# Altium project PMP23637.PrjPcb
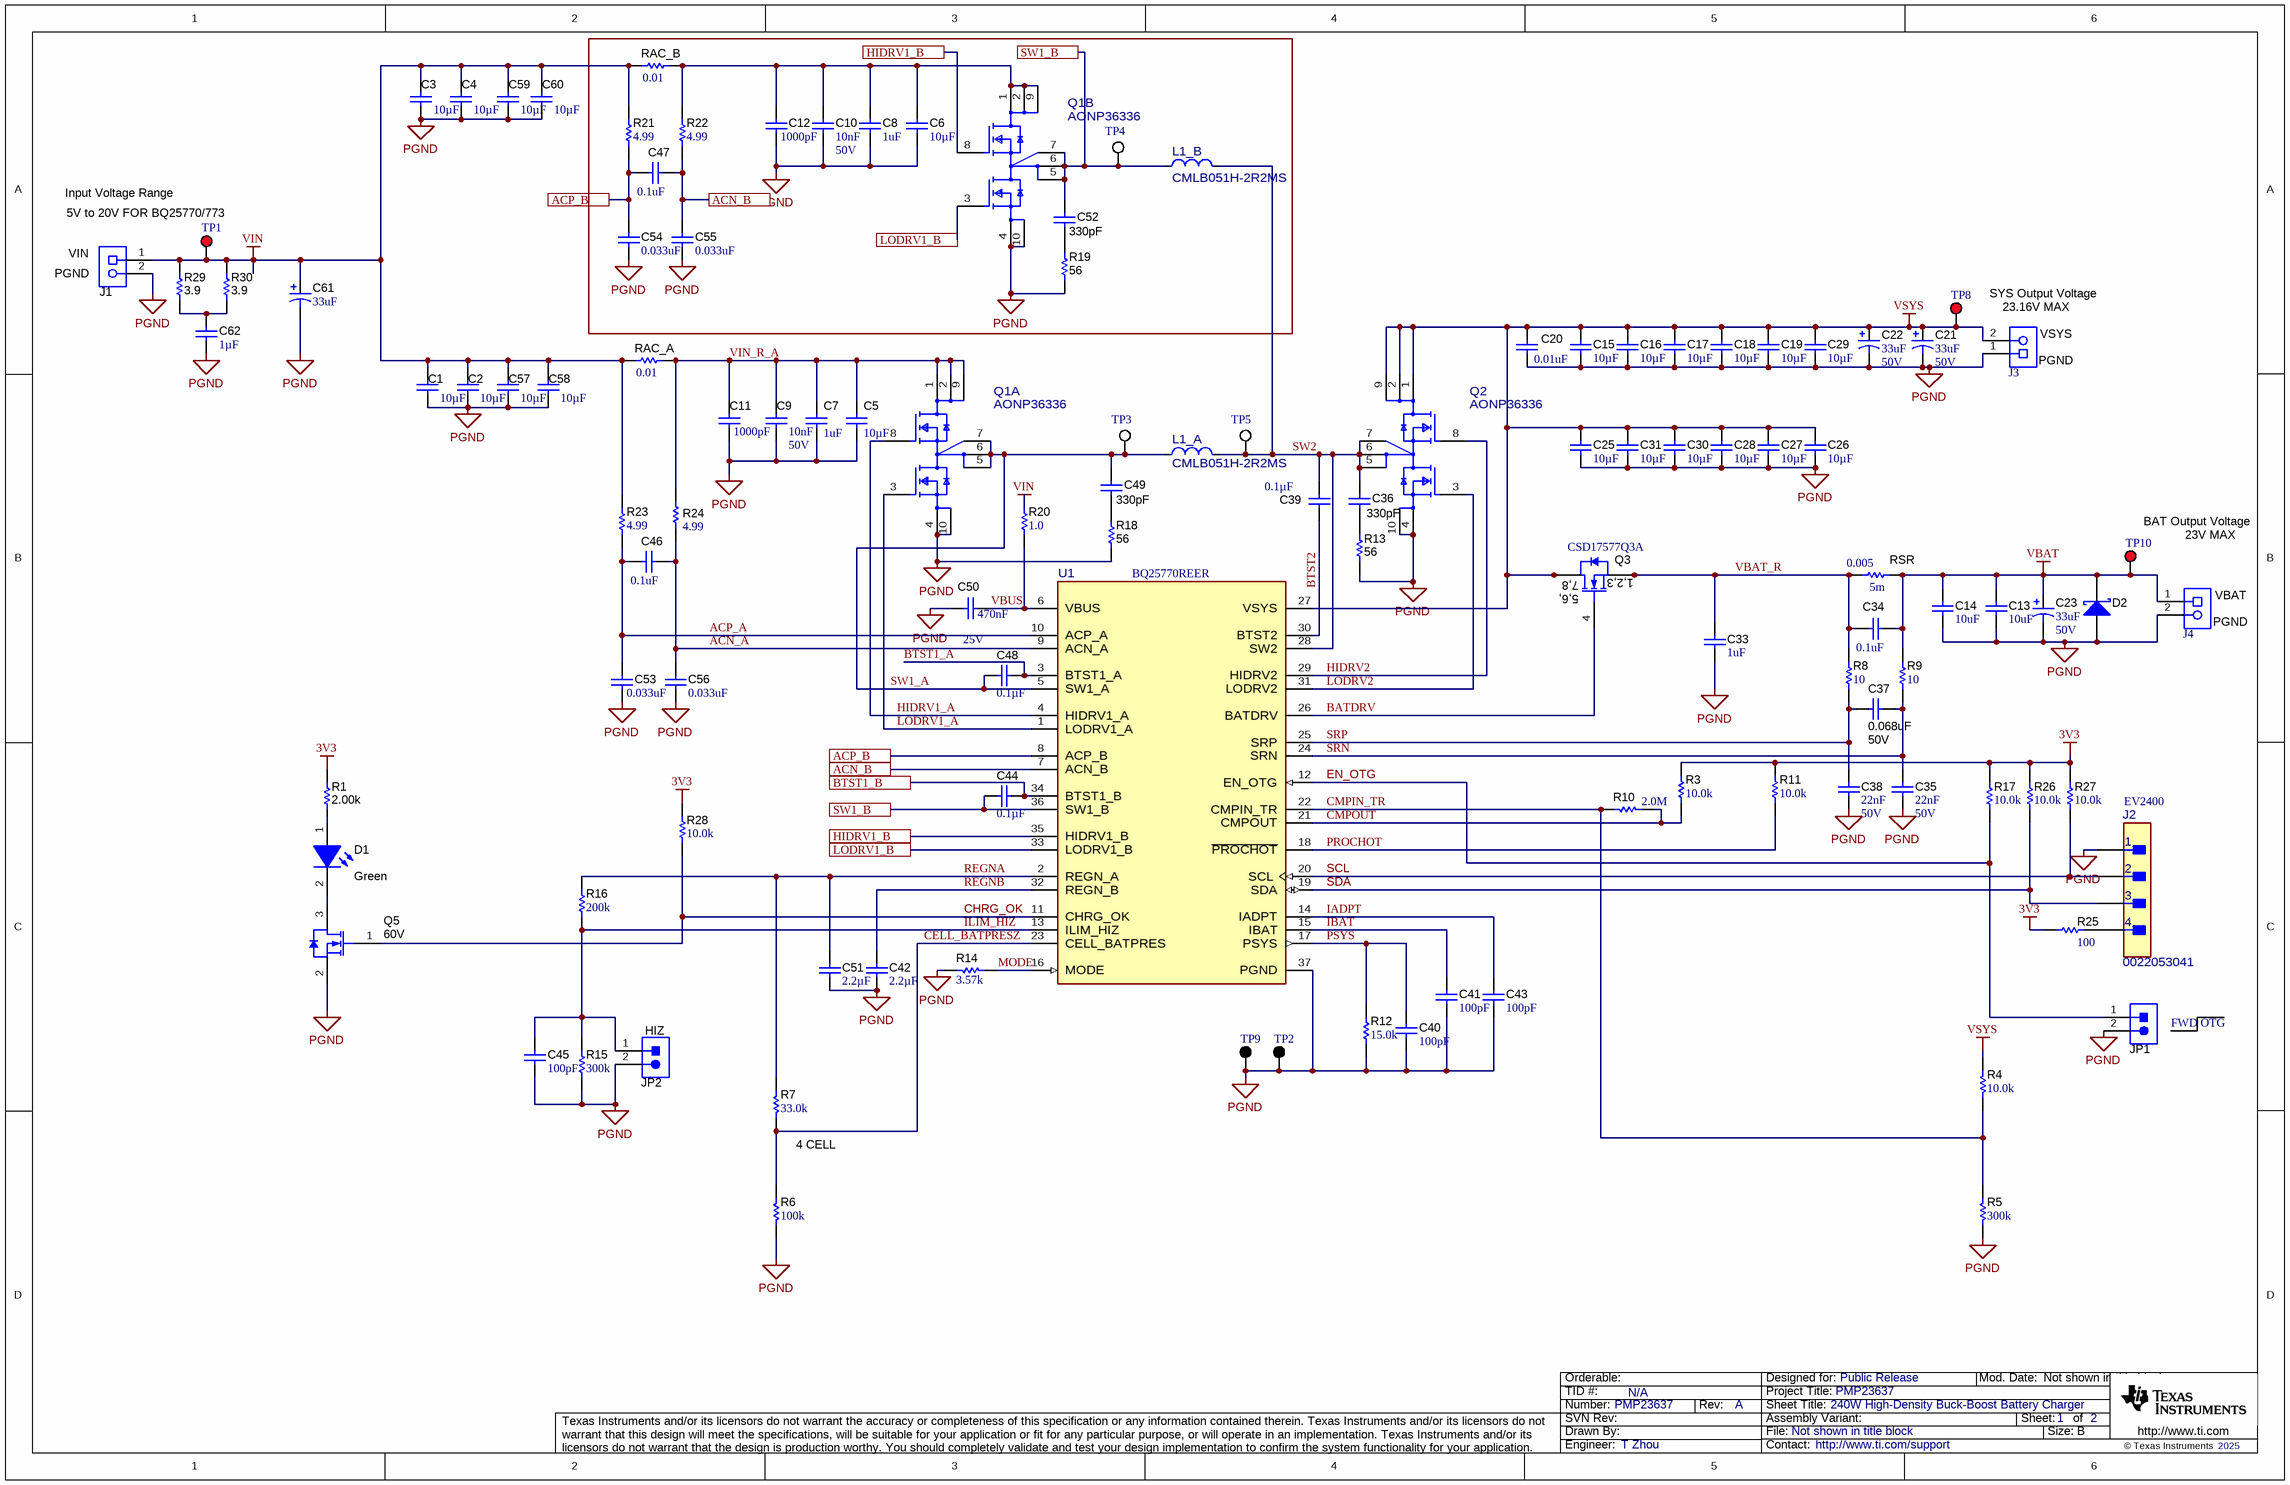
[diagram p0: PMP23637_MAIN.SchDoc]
CopyrightYear: 2025; PCB_Layout: T Zhou; PCB_Rev: A; PRJ_Customer: Public Release; PRJ_Engineer: T Zhou; PRJ_Number: PMP23637; PRJ_Title: PMP23637; SCH_Rev: A; TechSupport: http://www.ti.com/support; TID: N/A
2 sheets, 145 parts. Net scope: global (net labels, ports and power ports of the same name join across sheets).
Board file: PMP23637-PCB.PcbDoc
Sheets:
  PMP23637_MAIN.SchDoc
  PMP23637_Hardware.SchDoc

## Sheet PMP23637_MAIN.SchDoc: 240W High-Density Buck-Boost Battery Charger
size 431 x 279 mm; Date: Not shown in title block; ApprovedBy: Not shown in title block; CheckedBy: Not shown in title block; Author: Not shown in title block; CompanyName: Not shown in title block; Engineer: Not shown in title block; Organization: Not shown in title block; Address1: Not shown in title block; Address2: Not shown in title block; Address3: Not shown in title block; Address4: Not shown in title block; DocumentNumber: 1; Revision: Use project parameter SCH_Rev; SheetNumber: 1; SheetTotal: 2; PageSetup: Record=PageOptions¦CenterHorizontal=True¦CenterVertical=True¦PrintScale=1.00¦XCorrection=1.00¦YCorrection=1.00¦PrintKind=0¦BorderSize=5000000¦LeftOffset=0¦BottomOffset=0¦Orientation=2¦PaperLength=1000¦PaperWidth=1000¦Scale=100¦PaperSource=15¦PrintQuality=600¦MediaType=1¦DitherType=10¦PaperKind=Letter¦PrintScaleMode=1

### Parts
C1  ValueDisplayed: 10µF  [0805_HV1]  (hidden comment: C2012JB1V106K125AC)
C2  ValueDisplayed: 10µF  [0805_HV1]  (hidden comment: C2012JB1V106K125AC)
C3  ValueDisplayed: 10µF  [0805_HV1]  (hidden comment: C2012JB1V106K125AC)
C4  ValueDisplayed: 10µF  [0805_HV1]  (hidden comment: C2012JB1V106K125AC)
C5  ValueDisplayed: 10µF  [0805_HV1]  (hidden comment: C2012JB1V106K125AC)
C6  ValueDisplayed: 10µF  [0805_HV1]  (hidden comment: C2012JB1V106K125AC)
C7  ValueDisplayed: 1uF  [0603S]  (hidden comment: C1608X5R1H105K080AB)
C8  ValueDisplayed: 1uF  [0603S]  (hidden comment: C1608X5R1H105K080AB)
C9  Cap_F: 10nF  VDC_V: 50V  [0603S]  (hidden comment: C0603C103J5RACTU)
C10  Cap_F: 10nF  VDC_V: 50V  [0603S]  (hidden comment: C0603C103J5RACTU)
C11  ValueDisplayed: 1000pF  [0402S]  (hidden comment: 04025C102JAT2A)
C12  ValueDisplayed: 1000pF  [0402S]  (hidden comment: 04025C102JAT2A)
C13  ValueDisplayed: 10uF  [1206_190L]  (hidden comment: GMK316AB7106KL-TR)
C14  ValueDisplayed: 10uF  [1206_190L]  (hidden comment: GMK316AB7106KL-TR)
C15  ValueDisplayed: 10µF  [0805_HV1]  (hidden comment: C2012JB1V106K125AC)
C16  ValueDisplayed: 10µF  [0805_HV1]  (hidden comment: C2012JB1V106K125AC)
C17  ValueDisplayed: 10µF  [0805_HV1]  (hidden comment: C2012JB1V106K125AC)
C18  ValueDisplayed: 10µF  [0805_HV1]  (hidden comment: C2012JB1V106K125AC)
C19  ValueDisplayed: 10µF  [0805_HV1]  (hidden comment: C2012JB1V106K125AC)
C20  ValueDisplayed: 0.01uF  [0603S]  (hidden comment: C0603C103J5RACTU)
C21  ValueDisplayed: 33uF  VDC_V: 50V  [7343-43]  (hidden comment: T521X336M050ATE050)
C22  ValueDisplayed: 33uF  VDC_V: 50V  [7343-43]  (hidden comment: T521X336M050ATE050)
C23  ValueDisplayed: 33uF  VDC_V: 50V  [7343-43]  (hidden comment: T521X336M050ATE050)
C25  ValueDisplayed: 10µF  [0805_HV1]  (hidden comment: C2012JB1V106K125AC)
C26  ValueDisplayed: 10µF  [0805_HV1]  (hidden comment: C2012JB1V106K125AC)
C27  ValueDisplayed: 10µF  [0805_HV1]  (hidden comment: C2012JB1V106K125AC)
C28  ValueDisplayed: 10µF  [0805_HV1]  (hidden comment: C2012JB1V106K125AC)
C29  ValueDisplayed: 10µF  [0805_HV1]  (hidden comment: C2012JB1V106K125AC)
C30  ValueDisplayed: 10µF  [0805_HV1]  (hidden comment: C2012JB1V106K125AC)
C31  ValueDisplayed: 10µF  [0805_HV1]  (hidden comment: C2012JB1V106K125AC)
C33  ValueDisplayed: 1uF  [0603S]  (hidden comment: C1608X5R1H105K080AB)
C34  ValueDisplayed: 0.1uF  [0402S]  (hidden comment: GRM155R71H104ME14D)
C35  Cap_F: 22nF  VDC_V: 50V  [0402S]  (hidden comment: GRM155R71H223KA12D)
C36  ValueDisplayed: 330pF  [0603S]  (hidden comment: Capacitor)
C37  ValueDisplayed: 0.068uF  VDC_V: 50V  [0402S]  (hidden comment: CGA2B3X7R1H683K050BB)
C38  Cap_F: 22nF  VDC_V: 50V  [0402S]  (hidden comment: GRM155R71H223KA12D)
C39  ValueDisplayed: 0.1µF  [0402S]  (hidden comment: CGA2B3X7R1E104K050BB)
C40  ValueDisplayed: 100pF  [0402S]  (hidden comment: GRM1555C1H101JA01D)
C41  ValueDisplayed: 100pF  [0402S]  (hidden comment: GRM1555C1H101JA01D)
C42  ValueDisplayed: 2.2µF  [0402S]  (hidden comment: GRM155R61E225ME15D)
C43  ValueDisplayed: 100pF  [0402S]  (hidden comment: GRM1555C1H101JA01D)
C44  ValueDisplayed: 0.1µF  [0402S]  (hidden comment: CGA2B3X7R1E104K050BB)
C45  ValueDisplayed: 100pF  [0402S]  (hidden comment: GRM1555C1H101JA01D)
C46  ValueDisplayed: 0.1uF  [0402S]  (hidden comment: C1005X7R1H104K050BE)
C47  ValueDisplayed: 0.1uF  [0402S]  (hidden comment: C1005X7R1H104K050BE)
C48  ValueDisplayed: 0.1µF  [0402S]  (hidden comment: CGA2B3X7R1E104K050BB)
C49  ValueDisplayed: 330pF  [0603S]  (hidden comment: Capacitor)
C50  Cap_F: 470nF  VDC_V: 25V  [0402S]  (hidden comment: GRM155R61E474KE01D)
C51  ValueDisplayed: 2.2µF  [0402S]  (hidden comment: GRM155R61E225ME15D)
C52  ValueDisplayed: 330pF  [0603S]  (hidden comment: Capacitor)
C53  ValueDisplayed: 0.033uF  [0402S]  (hidden comment: CGA2B3X7R1H333K050BB)
C54  ValueDisplayed: 0.033uF  [0402S]  (hidden comment: CGA2B3X7R1H333K050BB)
C55  ValueDisplayed: 0.033uF  [0402S]  (hidden comment: CGA2B3X7R1H333K050BB)
C56  ValueDisplayed: 0.033uF  [0402S]  (hidden comment: CGA2B3X7R1H333K050BB)
C57  ValueDisplayed: 10µF  [0805_HV1]  (hidden comment: C2012JB1V106K125AC)
C58  ValueDisplayed: 10µF  [0805_HV1]  (hidden comment: C2012JB1V106K125AC)
C59  ValueDisplayed: 10µF  [0805_HV1]  (hidden comment: C2012JB1V106K125AC)
C60  ValueDisplayed: 10µF  [0805_HV1]  (hidden comment: C2012JB1V106K125AC)
C61  ValueDisplayed: 33uF  [7343-43]  (hidden comment: T521X336M050ATE050)
C62  ValueDisplayed: 1µF  [0805_HV1]  (hidden comment: GCM21BR71H105KA03K)
D1  value Green  [LED_LTST-C190]  (hidden comment: LED)
D2  B240A-13-F  [SMA]  (value not drawn)
J1  Receptacle_2x1  [On-Shore_ED120_2DS]  (value not drawn)
J2  0022053041  [FP-22-05-3041_HDR4-MFG]
J3  ED120/2DS  [On-Shore_ED120_2DS]  (value not drawn)
J4  ED120/2DS  [On-Shore_ED120_2DS]  (value not drawn)
JP1  TSW-102-07-G-S  [TSW-102-07-G-S]  (value not drawn)
JP2  TSW-102-07-G-S  [TSW-102-07-G-S]  (value not drawn)
L1_A  CMLB051H-2R2MS  [FP-CMLB051H-2R2MS_SMT25MM4_5MM2-MFG]
L1_B  CMLB051H-2R2MS  [FP-CMLB051H-2R2MS_SMT25MM4_5MM2-MFG]
Q1A  AONP36336  [FP-AONP36336_DFN3.3x3.3B-MFG]
Q1B  AONP36336  [FP-AONP36336_DFN3.3x3.3B-MFG]
Q2  AONP36336  [FP-AONP36336_DFN3.3x3.3B-MFG]
Q3  CSD17577Q3A  [DNH0008A]
Q5  value 60V  [SOT-23L]  (hidden comment: MOSFET_N_D3G1S2)
R1  value 2.00k  [0603S]  (hidden comment: Resistor)
R3  value 10.0k  [0402S]  (hidden comment: CRCW040210K0FKED)
R4  value 10.0k  [0402S]  (hidden comment: CRCW040210K0FKED)
R5  ValueDisplayed: 300k  [0402S]  (hidden comment: CRCW0402300KFKED)
R6  ValueDisplayed: 100k  [0402S]  (hidden comment: RC0402FR-07100KL)
R7  ValueDisplayed: 33.0k  [0402S]  (hidden comment: RC0402FR-0733KL)
R8  ValueDisplayed: 10  [0402S]  (hidden comment: CRCW040210R0JNED)
R9  ValueDisplayed: 10  [0402S]  (hidden comment: CRCW040210R0JNED)
R10  ValueDisplayed: 2.0M  [0402S]  (hidden comment: CRCW04022M00JNED)
R11  value 10.0k  [0402S]  (hidden comment: CRCW040210K0FKED)
R12  value 15.0k  [0402S]  (hidden comment: CRCW040215K0FKED)
R13  ValueDisplayed: 56  [0603S]  (hidden comment: Resistor)
R14  ValueDisplayed: 3.57k  [0402S]  (hidden comment: CRCW04023K57FKED)
R15  ValueDisplayed: 300k  [0402S]  (hidden comment: CRCW0402300KFKED)
R16  ValueDisplayed: 200k  [0402S]  (hidden comment: CRCW0402200KFKED)
R17  value 10.0k  [0402S]  (hidden comment: CRCW040210K0FKED)
R18  ValueDisplayed: 56  [0603S]  (hidden comment: Resistor)
R19  ValueDisplayed: 56  [0603S]  (hidden comment: Resistor)
R20  ValueDisplayed: 1.0  [0603S]  (hidden comment: CRCW06031R00JNEA)
R21  ValueDisplayed: 4.99  [0402S]  (hidden comment: Resistor)
R22  ValueDisplayed: 4.99  [0402S]  (hidden comment: Resistor)
R23  ValueDisplayed: 4.99  [0402S]  (hidden comment: Resistor)
R24  ValueDisplayed: 4.99  [0402S]  (hidden comment: Resistor)
R25  ValueDisplayed: 100  [0402S]  (hidden comment: CRCW0402100RJNED)
R26  value 10.0k  [0402S]  (hidden comment: CRCW040210K0FKED)
R27  value 10.0k  [0402S]  (hidden comment: CRCW040210K0FKED)
R28  ValueDisplayed: 10.0k  [0402S]  (hidden comment: Resistor)
R29  value 3.9  [1206L]  (hidden comment: Resistor)
R30  value 3.9  [1206L]  (hidden comment: Resistor)
RAC_A  ValueDisplayed: 0.01  [1206L]  (hidden comment: WSLP1206R0100FEA)
RAC_B  ValueDisplayed: 0.01  [1206L]  (hidden comment: WSLP1206R0100FEA)
RSR  Res_ohm: 5m  ValueDisplayed: 0.005  [2010L]  (hidden comment: CSNL2010FT5L00)
TP1  5010  [Keystone5010]  (value not drawn)
TP2  5011  [Keystone5011]  (value not drawn)
TP3  5012  [Keystone5012]  (value not drawn)
TP4  5012  [Keystone5012]  (value not drawn)
TP5  5012  [Keystone5012]  (value not drawn)
TP8  5010  [Keystone5010]  (value not drawn)
TP9  5011  [Keystone5011]  (value not drawn)
TP10  5010  [Keystone5010]  (value not drawn)
U1  BQ25770REER  [REE0036A-MFG]

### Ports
ACN_B, ACP_B, BTST1_B, HIDRV1_B, LODRV1_B, SW1_B

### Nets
3V3: R1.2 R3.2 R11.1 R17.2 R25.1 R26.2 R27.2 R28.1
PGND: C1.2 C2.2 C3.2 C4.2 C5.2 C6.2 C7.2 C8.2 C9.2 C10.2 C11.2 C12.2 C13.2 C14.2 C15.2 C16.2 C17.2 C18.2 C19.2 C20.2 C21.2(-) C22.2(-) C23.2(-) C25.2 C26.2 C27.2 C28.2 C29.2 C30.2 C31.2 C33.2 C35.2 C38.2 C40.2 C41.2 C42.1 C43.2 C45.2 C50.2 C51.2 C53.2 C54.2 C55.2 C56.2 C57.2 C58.2 C59.2 C60.2 C61.2(-) C62.2 D2.2(A) J1.2 J2.1 J3.1 J4.2 JP1.2 JP2.2 Q1A.4(S2) Q1A.10(S2) Q1B.4(S2) Q1B.10(S2) Q2.4(S2) Q2.10(S2) Q5.2(S) R5.1 R6.1 R12.2 R13.1 R14.1 R15.2 R18.1 R19.1 TP2.1 TP9.1 U1.37(PGND)
VBAT: C13.1 C14.1 C23.1(+) C34.2 D2.1(K) J4.1 R9.2 RSR.2 TP10.1
VIN: C1.1 C2.1 C3.1 C4.1 C57.1 C58.1 C59.1 C60.1 C61.1(+) J1.1 R20.2 R21.2 R23.2 R29.2 R30.2 RAC_A.1 RAC_B.1 TP1.1
VSYS: C15.1 C16.1 C17.1 C18.1 C19.1 C20.1 C21.1(+) C22.1(+) C25.1 C26.1 C27.1 C28.1 C29.1 C30.1 C31.1 J3.2 Q2.1(D1) Q2.2(D1) Q2.9(D1) Q3.5(D) Q3.6(D) Q3.7(D) Q3.8(D) Q3.9(D) R4.1 TP8.1 U1.27(VSYS)
ACN_A: C46.2 C56.1 R24.1 U1.9(ACN_A)
ACN_B: C47.2 C55.1 R22.1 U1.7(ACN_B) ; port ACN_B
ACP_A: C46.1 C53.1 R23.1 U1.10(ACP_A)
ACP_B: C47.1 C54.1 R21.1 U1.8(ACP_B) ; port ACP_B
BATDRV: Q3.4(G) U1.26(BATDRV)
BTST1_A: C48.1 U1.3(BTST1_A)
BTST1_B: C44.1 U1.34(BTST1_B) ; port BTST1_B
BTST2: C39.1 U1.30(BTST2)
CELL_BATPRESZ: R6.2 R7.1 U1.23(CELL_BATPRES)
CHRG_OK: Q5.1(G) R28.2 U1.11(CHRG_OK)
CMPIN_TR: R4.2 R5.2 R10.2 U1.22(CMPIN_TR)
CMPOUT: R3.1 R10.1 U1.21(CMPOUT)
EN_OTG: JP1.1 R17.1 U1.12(EN_OTG)
HIDRV1_A: Q1A.8(G1) U1.4(HIDRV1_A)
HIDRV1_B: Q1B.8(G1) U1.35(HIDRV1_B) ; port HIDRV1_B
HIDRV2: Q2.8(G1) U1.29(HIDRV2)
IADPT: C43.1 U1.14(IADPT)
IBAT: C41.1 U1.15(IBAT)
ILIM_HIZ: C45.1 JP2.1 R15.1 R16.2 U1.13(ILIM_HIZ)
LODRV1_A: Q1A.3(G2) U1.1(LODRV1_A)
LODRV1_B: Q1B.3(G2) U1.33(LODRV1_B) ; port LODRV1_B
LODRV2: Q2.3(G2) U1.31(LODRV2)
MODE: R14.2 U1.16(MODE)
PROCHOT: R11.2 U1.18(~{PROCHOT})
PSYS: C40.1 R12.1 U1.17(PSYS)
REGNA: C51.1 R7.2 R16.1 U1.2(REGN_A)
REGNB: C42.2 U1.32(REGN_B)
SCL: J2.2 R27.1 U1.20(SCL)
SDA: J2.3 R26.1 U1.19(SDA)
SRN: C35.1 C37.2 R9.1 U1.24(SRN)
SRP: C37.1 C38.1 R8.1 U1.25(SRP)
SW1_A: C48.2 C49.1 L1_A.1 Q1A.5(D2/S1) Q1A.6(D2/S1) Q1A.7(S1(sense)) TP3.1 U1.5(SW1_A)
SW1_B: C44.2 C52.1 L1_B.1 Q1B.5(D2/S1) Q1B.6(D2/S1) Q1B.7(S1(sense)) TP4.1 U1.36(SW1_B) ; port SW1_B
SW2: C36.1 C39.2 L1_A.2 L1_B.2 Q2.5(D2/S1) Q2.6(D2/S1) Q2.7(S1(sense)) TP5.1 U1.28(SW2)
VBAT_R: C33.1 C34.1 Q3.1(S) Q3.2(S) Q3.3(S) R8.2 RSR.1
VBUS: C50.1 R20.1 U1.6(VBUS)
VIN_R_A: C5.1 C7.1 C9.1 C11.1 Q1A.1(D1) Q1A.2(D1) Q1A.9(D1) R24.2 RAC_A.2
NetC6_1: C6.1 C8.1 C10.1 C12.1 Q1B.1(D1) Q1B.2(D1) Q1B.9(D1) R22.2 RAC_B.2
NetC36_2: C36.2 R13.2
NetC49_2: C49.2 R18.2
NetC52_2: C52.2 R19.2
NetC62_1: C62.1 R29.1 R30.1
NetD1_1: D1.1(A) R1.1
NetD1_2: D1.2(K) Q5.3(D)
NetJ2_4: J2.4 R25.2

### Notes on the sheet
- Input Voltage Range
- 5V to 20V FOR BQ25770/773
- (near J1) PGND
- (near J1) VIN
- (near J3) 23.16V MAX
- SYS Output Voltage
- (near J3) VSYS
- (near J3) PGND
- (near TP10) BAT Output Voltage
- 23V MAX
- (near J4) PGND
- (near J4) VBAT
- EV2400
- (near JP2) HIZ
- (near JP1) FWD OTG
- (near R7) 4 CELL

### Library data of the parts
C1-C6 C57-C60 = CMP-0085894-1: CAP, CERM, 10 µF, 50 V,+/- 10%, JB, 0805; PartNumber: GRM21BR61H106KE43L; Manufacturer: muRata; Polarized: N; Value: 10uF; U/M: EA; Value2: 50V; TaMin_C: -25°C; TaMax_C: 85°C; Cap_Case: 0805; SizeArea_mm2: 2.5; SizeAreaWB_mm2: 6.75; SizeX_mm: 2; SizeY_mm: 1.25; SizeZ_mm: 1.45; AEC Category: Q200
C7 C8 = CMP-0007011-5: CAP, CERM, 1 uF, 50 V, +/- 10%, X5R, 0603; Manufacturer: TDK; Polarized: N; Value: 1uF; U/M: EA; Cap_F: 1µF; ESR_ohm: 5.522m; Value1: 0.005522 ohm; Value2: 50V; IRMS_A: 2.2162A; TaMin_C: -55°C; TaMax_C: 85°C; Cap_Case: 0603; SizeArea_mm2: 1.28; SizeAreaWB_mm2: 4.68; SizeX_mm: 1.6; SizeY_mm: 0.8; SizeZ_mm: 1; AEC Category: Q200
C9 C10 = CMP-0006850-4: CAP, CERM, 0.01 uF, 50 V, +/- 5%, X7R, 0603; Manufacturer: Kemet; Polarized: N; Value: 0.01uF; U/M: EA; Value1: Unknown; TaMin_C: -55°C; TaMax_C: 125°C; Cap_Case: 0603; AEC Category: Q200; SizeAreaWB_mm2: 4.68; SizeZ_mm: 1; SizeX_mm: 1.6; SizeY_mm: 0.8; SizeArea_mm2: 1.28
C11 C12 = CMP-0861060-1: CAP, CERM, 1000 pF, 50 V,+/- 5%, X7R, 0402; Manufacturer: AVX; Polarized: N; Value: 1000pF; U/M: EA; Cap_F: 1nF; VDC_V: 50V; TaMin_C: -55°C; TaMax_C: 125°C; Cap_Case: 0402; AEC Category: Q200; SizeArea_mm2: 0.5; SizeAreaWB_mm2: 3; SizeX_mm: 1; SizeZ_mm: 0.6; Green_Lifecycle: Active; Green_REACh: Passed
C13 C14 = CMP-0008822-2: CAP, CERM, 10 uF, 35 V, +/- 10%, X7R, 1206_190; Manufacturer: Taiyo Yuden; Polarized: N; Value: 10uF; U/M: EA; Cap_F: 10µF; Value1: Unknown; VDC_V: 35V; TaMin_C: -55°C; TaMax_C: 125°C; Cap_Case: 1206; SizeArea_mm2: 5.12; SizeAreaWB_mm2: 10.92; SizeX_mm: 3.2; SizeY_mm: 1.6; SizeZ_mm: 1.9; AEC Category: Q200
C15-C19 C25-C31 = CMP-0085894-1: CAP, CERM, 10 µF, 50 V,+/- 10%, JB, 0805; PartNumber: GRM21BR61H106KE43L; Manufacturer: muRata; Polarized: N; Value: 10uF; U/M: EA; VDC_V: 50V; TaMin_C: -25°C; TaMax_C: 85°C; Cap_Case: 0805; SizeArea_mm2: 2.5; SizeAreaWB_mm2: 6.75; SizeX_mm: 2; SizeY_mm: 1.25; SizeZ_mm: 1.45; AEC Category: Q200
C20 = CMP-0006850-4: CAP, CERM, 0.01 uF, 50 V, +/- 5%, X7R, 0603; Manufacturer: Kemet; Polarized: N; Value: 0.01uF; U/M: EA; Cap_F: 10nF; Value1: Unknown; VDC_V: 50V; TaMin_C: -55°C; TaMax_C: 125°C; Cap_Case: 0603; SizeAreaWB_mm2: 4.68; SizeZ_mm: 1; SizeX_mm: 1.6; SizeY_mm: 0.8; SizeArea_mm2: 1.28; AEC Category: Q200
C21-C23 = CMP-0012653-3: CAP, Tantalum Polymer, 33 uF, 50 V, +/- 20%, 0.05 ohm, 7343-43 SMD; Manufacturer: Kemet; Polarized: Y; CompType: Capacitor; Value: 33uF; Cap_F: 33µF; ESR_ohm: 50m; IRMS_A: 2.2A; TaMin_C: -55°C; TaMax_C: 125°C; Cap_Case: 7.3x4.3x4.3mm; AEC Category: Q200; AEC Qualified: N; SizeAreaWB_mm2: 58.59; SizeArea_mm2: 31.39; SizeX_mm: 7.3; SizeY_mm: 4.3
C33 = CMP-0007011-5: CAP, CERM, 1 uF, 50 V, +/- 10%, X5R, 0603; Manufacturer: TDK; Polarized: N; Value: 1uF; U/M: EA; Cap_F: 1µF; ESR_ohm: 5.522m; Value1: 0.005522 ohm; VDC_V: 50V; IRMS_A: 2.2162A; TaMin_C: -55°C; TaMax_C: 85°C; Cap_Case: 0603; SizeAreaWB_mm2: 4.68; SizeZ_mm: 1; SizeX_mm: 1.6; SizeY_mm: 0.8; SizeArea_mm2: 1.28; AEC Category: Q200
C34 = CMP-0006675-2: CAP, CERM, 0.1 uF, 50 V, +/- 20%, X7R, 0402; Manufacturer: MuRata; Polarized: N; Value: 0.1uF; U/M: EA; Cap_F: 100nF; Value1: Unknown; VDC_V: 50V; TaMin_C: -55°C; TaMax_C: 125°C; Cap_Case: 0402; SizeAreaWB_mm2: 3; SizeZ_mm: 0.6; SizeX_mm: 1; SizeY_mm: 0.5; AEC Category: Q200
C35 C38 = CMP-0006684-2: CAP, CERM, 0.022 uF, 50 V, +/- 10%, X7R, 0402; Manufacturer: MuRata; Polarized: N; U/M: EA; Value1: Unknown; TaMin_C: -55°C; TaMax_C: 125°C; Cap_Case: 0402; AEC Category: Q200; SizeArea_mm2: 0.5; SizeAreaWB_mm2: 3; SizeX_mm: 1; SizeZ_mm: 0.6
C36 C49 C52 = CMP-0007449-4: CAP, CERM, 330 pF, 50 V, +/- 10%, X7R, 0603; PartNumber: GRM188R71H331KA01D; Manufacturer: MuRata; Polarized: N; Value: 330pF; U/M: EA; Value1: Unknown; VDC_V: 50V; TaMin_C: -55°C; TaMax_C: 125°C; Cap_Case: 0603; SizeAreaWB_mm2: 4.68; SizeZ_mm: 1; SizeX_mm: 1.6; SizeY_mm: 0.8; SizeArea_mm2: 1.28; AEC Category: Q200
C37 = CMP-0006331-2: CAP, CERM, 0.068 uF, 50 V, +/- 10%, X7R, AEC-Q200 Grade 1, 0402; Manufacturer: TDK; Polarized: N; U/M: EA; Cap_F: 68nF; ESR_ohm: 0.05606; Value1: 0.05606 ohm; IRMS_A: 684.724mA; TaMin_C: -55°C; TaMax_C: 125°C; Cap_Case: 0402; SizeAreaWB_mm2: 3; SizeZ_mm: 0.6; SizeX_mm: 1; SizeY_mm: 0.5; AEC Qualified: Y; AEC Category: Q200
C39 C44 C48 = CMP-0080610-1: CAP, CERM, 0.1 µF, 25 V,+/- 10%, X7R, AEC-Q200 Grade 1, 0402; Manufacturer: TDK; Polarized: N; Value: 0.1uF; U/M: EA; Cap_F: 100nF; VDC_V: 25V; TaMin_C: -55°C; TaMax_C: 125°C; Cap_Case: 0402; SizeAreaWB_mm2: 3; SizeZ_mm: 0.6; SizeX_mm: 1; SizeY_mm: 0.5; AEC Qualified: Y; AEC Category: Q200
C40 C41 C43 C45 = CMP-0006410-2: CAP, CERM, 100 pF, 50 V, +/- 5%, C0G/NP0, 0402; Manufacturer: MuRata; Polarized: N; Value: 100pF; U/M: EA; Value1: Unknown; VDC_V: 50V; TaMin_C: -55°C; TaMax_C: 125°C; Cap_Case: 0402; SizeAreaWB_mm2: 3; SizeZ_mm: 0.6; SizeX_mm: 1; SizeY_mm: 0.5; AEC Category: Q200
C42 C51 = CMP-0081010-1: CAP, CERM, 2.2 µF, 25 V,+/- 20%, X5R, 0402; Manufacturer: MuRata; Polarized: N; Value: 2.2uF; U/M: EA; VDC_V: 25V; TaMin_C: -55°C; TaMax_C: 85°C; Cap_Case: 0402; SizeAreaWB_mm2: 3; SizeZ_mm: 0.6; SizeX_mm: 1; SizeY_mm: 0.5; AEC Category: Q200
C46 C47 = CMP-0064946-2: CAP, CERM, 0.1 uF, 50 V,+/- 10%, X7R, 0402; Manufacturer: TDK; Polarized: N; Value: 0.1uF; U/M: EA; Cap_F: 100nF; Value1: Unknown; VDC_V: 50V; TaMin_C: -55°C; TaMax_C: 125°C; Cap_Case: 0402; AEC Category: Q200; SizeAreaWB_mm2: 3; SizeZ_mm: 0.6; SizeX_mm: 1; SizeY_mm: 0.5
C50 = CMP-0064928-2: CAP, CERM, 0.47 uF, 25 V,+/- 10%, X5R, 0402; Manufacturer: MuRata; Value: 0.47uF; AEC Qualified: N; SizeZ_mm: 0.6; TaMin_C: -55°C; SizeAreaWB_mm2: 3; Value1: Unknown; U/M: EA; TaMax_C: 85°C; SizeX_mm: 1; SizeY_mm: 0.5; Cap_Case: 0402; AEC Category: Q200
C53-C56 = CMP-0006329-2: CAP, CERM, 0.033 uF, 50 V, +/- 10%, X7R, AEC-Q200 Grade 1, 0402; Manufacturer: TDK; Polarized: N; U/M: EA; Cap_F: 33nF; ESR_ohm: 98.477m; Value1: 0.098477 ohm; VDC_V: 50V; IRMS_A: 530.78mA; TaMin_C: -55°C; TaMax_C: 125°C; Cap_Case: 0402; AEC Category: Q200; AEC Qualified: Y; AEC Grade: 1; SizeArea_mm2: 0.5; SizeAreaWB_mm2: 3; SizeZ_mm: 0.6
C61 = CMP-0012653-3: CAP, Tantalum Polymer, 33 uF, 50 V, +/- 20%, 0.05 ohm, 7343-43 SMD; Manufacturer: Kemet; Polarized: Y; CompType: Capacitor; Value: 33uF; Cap_F: 33µF; VDC_V: 50V; ESR_ohm: 50m; IRMS_A: 2.2A; TaMin_C: -55°C; TaMax_C: 125°C; Cap_Case: 7.3x4.3x4.3mm; AEC Category: Q200; AEC Qualified: N; SizeAreaWB_mm2: 58.59; SizeArea_mm2: 31.39; SizeX_mm: 7.3; SizeY_mm: 4.3
C62 = CMP-0086249-1: CAP, CERM, 1 µF, 50 V,+/- 10%, X7R, AEC-Q200 Grade 1, 0805; Manufacturer: MuRata; Polarized: N; Value: 1uF; U/M: EA; VDC_V: 50V; TaMin_C: -55°C; TaMax_C: 125°C; Cap_Case: 0805; SizeAreaWB_mm2: 6.75; SizeZ_mm: 1.45; SizeX_mm: 2; SizeY_mm: 1.25; SizeArea_mm2: 2.5; AEC Qualified: Y; AEC Category: Q200; AEC Grade: 1
D1 = CMP-0002827-3: LED, Green, SMD; Manufacturer: Lite-On; PartNumber: LTST-C190GKT; Vf_V: 2.1V; Io_A: 20mA; Power_TotalModule: 100mW; Value1: 0.1W
D2 = CMP-0028403-2: Diode, Schottky, 40 V, 2 A, SMA; Manufacturer: Diodes Inc.; Vf_V: 500mV; Value: 40V; Value1: 2A; Value2: 0.5V; TJmax_C: 150°C; RJC_CperW: 20; Green_REACh: Passed; SizeAreaWB_mm2: 37.3428; SizeZ_mm: 2.87; SizeX_mm: 5.59; SizeArea_mm2: 16.3228; SizeY_mm: 2.92; Green_Lifecycle: Active; AEC Category: Q101
J1 = CMP-0074910-1: Terminal Block, 5.08 mm, 2x1, Brass, TH; PartNumber: ED120/2DS; Manufacturer: On-Shore Technology; U/M: EA; Cert_VDE: Y; CNHeader: False; Current_A: 15A; Green_Lifecycle: Not Set; Shrouded: N; Gender: Female; Green_REACh: Incomplete; Voltage_V: 300V; Row_Count: 1; Pitch_mm: 5.08; CT: True
J2 = CMP-0089047-2: Connector Header Through Hole, Right Angle 4 position 0.100" (2.54mm); Manufacturer: Molex; Row_Count: 1; Current_A: 4A; ContactFinish: Tin,Nickel; Voltage_V: 500V
J3 J4 = CMP-0074910-1: Terminal Block, 5.08 mm, 2x1, Brass, TH; Manufacturer: On-Shore Technology; Cert_VDE: Y; CNHeader: False; Current_A: 15A; Green_Lifecycle: Not Set; Shrouded: N; Gender: Female; Green_REACh: Incomplete; Voltage_V: 300V; Row_Count: 1; Pitch_mm: 5.08; CT: True
JP1 JP2 = CMP-0075405-3: Header, 100mil, 2x1, Gold, TH; Manufacturer: Samtec; Green_REACh: Passed; Green_Lifecycle: Active; Cert_CSA: Y; Cert_CULUS: N; Current_A: 6.3A; Gender: Male; Pitch_mm: 2.54; Row_Count: 1; Voltage_V: 550V
L1_A L1_B = CMP-0097234-1: 2.2 µH Shielded Inductor 5.2 A 35mOhm Max; Manufacturer: Cyntec; AEC Qualified: No; DCR_ohm: 35m; Ind_H: 2.2µH; Irms: 5.2A; Isat: 6A; Material: Metal Dust; SizeZ_mm: 1.8mm; Value: 2.2uH; Test Frequency: 100kHz; Tolerance_%: 20%; Standoff Height: 0mm
Q1A Q1B Q2 = CMP-0121471-1: Mosfet Array 30V 50A (Tc) 3.4W (Ta), 33W (Tc), 3.1W (Ta), 30W (Tc) Surface Mount 8-DFN-EP (3.3x3.3); Manufacturer: Alpha & Omega Semiconductor; AEC Qualified: No; SizeZ_mm: 0.85mm; VdsMax_V: 1V; Vgs_V: 12V; ChMode: False; Number Of Channels: 2; Power_W: 3.4/3.1W; Pulse Drain Current: 110/88A; Reverse Recovery Charge: 19/14nC; Reverse Recovery Time: 11/10ns; Rthja Max: 52/55°C/W; Standoff Height: 0mm; Threshold Vgs Max: 1.9V; Threshold Vgs Min: 1.1V; TJmax_C: +150°C; Transconductance: 100S; Turn Off Delay Time: 21.5ns; Turn On Delay Time: 5.5/3.5ns; Typ Forward Diode Voltage: 0.7V
Q3 = CMP-0000589-2: MOSFET, N-CH, 30 V, 19 A, DNH0008A (VSONP-8); Manufacturer: Texas Instruments; Alternate Manufacturer: None; VdsMax_V: 30V; Rdson45_ohm: 6.4m; QgTyp_nC: 13; Vgs_V: 20V; IdsMax_A: 19A; AEC Qualified: N; SizeZ_mm: 0.9; Value2: 13 nC; Value1: 0.006; SizeX_mm: 3.3; SizeAreaWB_mm2: 18.49; Value: 30V; SizeArea_mm2: 10.89; AEC Category: Q101; ChMode: Enhancement
Q5 = CMP-0000772-1: MOSFET, N-CH, 60 V, 0.26 A, SOT-23; PartNumber: 2N7002ET1G; Manufacturer: ON Semiconductor; Alternate Manufacturer: None; U/M: EA; ChType: N; Rdson45_ohm: 3; Value2: 0.81 nC; QgTyp_nC: 0.81; Vgs_V: 20V; IdsMax_A: 2.6dA; AEC Category: Q101; SizeZ_mm: 1.1; SizeX_mm: 2.5; SizeArea_mm2: 7.5; SizeAreaWB_mm2: 14
R1 = CMP-0022268-4: RES, 2.00 k, 1%, 0.1 W, AEC-Q200 Grade 0, 0603; PartNumber: CRCW06032K00FKEA; Manufacturer: Vishay-Dale; Res_ohm: 2k; Value_Code: 2k00; Power_W: 100mW; Value2: 0.1W; VDC_V: 75V; TempCo: 100 ppm/C; EIA_Code: E96; U/M: EA; SizeX_mm: 1.6; SizeY_mm: 0.8; SizeZ_mm: 1; SizeArea_mm2: 1.28; AEC Qualified: Y; AEC Category: Q200; AEC Grade: 0
R3 R4 R11 R17 R26 R27 = CMP-0025958-3: RES, 10.0 k, 1%, 0.063 W, AEC-Q200 Grade 0, 0402; Manufacturer: Vishay-Dale; Res_ohm: 10k; Value_Code: 10k0; Power_W: 63mW; Value2: 0.063W; VDC_V: 50V; TempCo: 100 ppm/C; EIA_Code: E96; SizeX_mm: 1; SizeY_mm: 0.5; SizeZ_mm: 0.6; AEC Qualified: Y; AEC Category: Q200; AEC Grade: 0
R5 R15 = CMP-0026279-2: RES, 300 k, 1%, 0.063 W, AEC-Q200 Grade 0, 0402; Manufacturer: Vishay-Dale; Value: 300k; Power_W: 63mW; Value2: 0.063W; VDC_V: 50V; TempCo: 100 ppm/C; SizeX_mm: 1; SizeY_mm: 0.5; SizeZ_mm: 0.6; AEC Qualified: Y; AEC Category: Q200; AEC Grade: 0
R6 = CMP-0026721-1: RES, 100 k, 1%, 0.0625 W, 0402; Manufacturer: Yageo America; Value: 100k; Power_W: 62.5mW; VDC_V: 50V; TempCo: 100 ppm/C; EIA_Code: E96; SizeX_mm: 1; SizeY_mm: 0.5; SizeZ_mm: 0.6; AEC Qualified: N; AEC Category: Q200; U/M: EA
R7 = CMP-0078584-1: RES, 33.0 k, 1%, 0.063 W, 0402; Manufacturer: Yageo America; Value: 33.0k; Res_ohm: 33k; Value_Code: 33k0; Power_W: 63mW; Value2: 0.063W; TempCo: 100 ppm/C; SizeX_mm: 1; SizeY_mm: 0.5; SizeZ_mm: 0.6; AEC Qualified: N; AEC Category: Q200
R8 R9 = CMP-0026827-3: RES, 10, 5%, 0.063 W, AEC-Q200 Grade 0, 0402; Manufacturer: Vishay-Dale; Value: 10; Value_Code: 10R0; Power_W: 63mW; Value2: 0.063W; VDC_V: 50V; TempCo: 200 ppm/C; EIA_Code: E24; SizeX_mm: 1; SizeY_mm: 0.5; SizeZ_mm: 0.6; AEC Qualified: Y; AEC Category: Q200; AEC Grade: 0
R10 = CMP-0026893-2: RES, 2.0 M, 5%, 0.063 W, AEC-Q200 Grade 0, 0402; Manufacturer: Vishay-Dale; Value: 2.0Meg; Res_ohm: 2M; Value_Code: 2M00; Power_W: 63mW; Value2: 0.063W; VDC_V: 50V; TempCo: 200 ppm/C; EIA_Code: E24; SizeX_mm: 1; SizeY_mm: 0.5; SizeZ_mm: 0.6; AEC Qualified: Y; AEC Category: Q200; AEC Grade: 0
R12 = CMP-0026027-3: RES, 15.0 k, 1%, 0.063 W, AEC-Q200 Grade 0, 0402; Manufacturer: Vishay-Dale; Res_ohm: 15k; Value_Code: 15k0; Power_W: 63mW; Value2: 0.063W; VDC_V: 50V; TempCo: 100 ppm/C; EIA_Code: E96; SizeX_mm: 1; SizeY_mm: 0.5; SizeZ_mm: 0.6; AEC Qualified: Y; AEC Category: Q200; AEC Grade: 0
R13 R18 R19 = CMP-0025829-4: RES, 56, 5%, 0.1 W, AEC-Q200 Grade 0, 0603; PartNumber: CRCW060356R0JNEA; Manufacturer: Vishay-Dale; Value: 56; Value_Code: 56R0; Power_W: 100mW; Value2: 0.1W; VDC_V: 75V; TempCo: 200 ppm/C; EIA_Code: E24; U/M: EA; SizeX_mm: 1.6; SizeY_mm: 0.8; SizeZ_mm: 1; SizeArea_mm2: 1.28; AEC Qualified: Y; AEC Category: Q200; AEC Grade: 0
R14 = CMP-0026336-2: RES, 3.57 k, 1%, 0.063 W, AEC-Q200 Grade 0, 0402; Manufacturer: Vishay-Dale; Value: 3.57k; Value_Code: 3k57; Power_W: 63mW; Value2: 0.063W; VDC_V: 50V; TempCo: 100 ppm/C; EIA_Code: E96; SizeX_mm: 1; SizeY_mm: 0.5; SizeZ_mm: 0.6; AEC Qualified: Y; AEC Category: Q200; AEC Grade: 0
R16 = CMP-0026158-2: RES, 200 k, 1%, 0.063 W, AEC-Q200 Grade 0, 0402; Manufacturer: Vishay-Dale; Value: 200k; Power_W: 63mW; Value2: 0.063W; VDC_V: 50V; TempCo: 100 ppm/C; EIA_Code: E96; SizeX_mm: 1; SizeY_mm: 0.5; SizeZ_mm: 0.6; AEC Qualified: Y; AEC Category: Q200; AEC Grade: 0
R20 = CMP-0025743-4: RES, 1.0, 5%, 0.1 W, AEC-Q200 Grade 0, 0603; Manufacturer: Vishay-Dale; Value: 1.0; Res_ohm: 1; Value_Code: 1R00; Power_W: 100mW; Value2: 0.1W; VDC_V: 75V; TempCo: 200 ppm/C; EIA_Code: E24; AEC Category: Q200; AEC Qualified: Y; AEC Grade: 0; SizeX_mm: 1.6; SizeY_mm: 0.8; SizeArea_mm2: 1.28
R21-R24 = CMP-0026434-2: RES, 4.99, 1%, 0.063 W, AEC-Q200 Grade 0, 0402; PartNumber: CRCW04024R99FKED; Manufacturer: Vishay-Dale; Value: 4.99; Value_Code: 4R99; Power_W: 63mW; Value2: 0.063W; VDC_V: 50V; TempCo: 100 ppm/C; EIA_Code: E96; AEC Category: Q200; AEC Qualified: Y; AEC Grade: 0; SizeArea_mm2: 0.5; SizeX_mm: 1; SizeZ_mm: 0.6
R25 = CMP-0026824-3: RES, 100, 5%, 0.063 W, AEC-Q200 Grade 0, 0402; Manufacturer: Vishay-Dale; Value: 100; Power_W: 63mW; VDC_V: 50V; TempCo: 200 ppm/C; AEC Qualified: Y; SizeZ_mm: 0.6; Value_Code: 100R; EIA_Code: E24; SizeX_mm: 1; SizeY_mm: 0.5; Value2: 0.063W; AEC Category: Q200; AEC Grade: 0
R28 = CMP-0025958-3: RES, 10.0 k, 1%, 0.063 W, AEC-Q200 Grade 0, 0402; PartNumber: CRCW040210K0FKED; Manufacturer: Vishay-Dale; Value: 10.0k; Res_ohm: 10k; Value_Code: 10k0; Power_W: 63mW; Value2: 0.063W; VDC_V: 50V; TempCo: 100 ppm/C; EIA_Code: E96; SizeX_mm: 1; SizeY_mm: 0.5; SizeZ_mm: 0.6; AEC Qualified: Y; AEC Category: Q200; AEC Grade: 0
R29 R30 = CMP-0018679-3: RES, 3.9, 5%, 0.25 W, AEC-Q200 Grade 0, 1206; PartNumber: CRCW12063R90JNEA; Manufacturer: Vishay-Dale; Value_Code: 3R90; Power_W: 250mW; Value2: 0.25W; VDC_V: 200V; TempCo: 200 ppm/C; EIA_Code: E24; U/M: EA; SizeX_mm: 3.2; SizeY_mm: 1.6; SizeZ_mm: 1.35; SizeArea_mm2: 5.12; AEC Qualified: Y; AEC Category: Q200; AEC Grade: 0
RAC_A RAC_B = CMP-0018570-2: RES, 0.01, 1%, 1 W, 1206; Manufacturer: Vishay-Dale; Value: 0.01; Res_ohm: 10m; Value_Code: R010; Power_W: 1W; TempCo: 75 ppm/C; EIA_Code: E96; SizeX_mm: 3.2; SizeY_mm: 1.6; SizeZ_mm: 1.35; SizeArea_mm2: 5.12; AEC Category: Q200; U/M: EA
RSR = CMP-0016512-2: RES, 0.005, 1%, 1.5 W, 2010; Manufacturer: Stackpole Electronics Inc; Value: 0.005; Power_W: 1.5W; TempCo: 50 ppm/C; SizeZ_mm: 1.66; Value_Code: 5L000; U/M: EA; EIA_Code: E96; SizeX_mm: 5; SizeY_mm: 2.5; SizeArea_mm2: 12.5; AEC Category: Q200
TP1 TP8 TP10 = CMP-0055147-2: Test Point, Multipurpose, Red, TH; Manufacturer: Keystone Electronics; CNHeader: FALSE; Green_Lifecycle: Active; Green_REACh: Passed; CT: TRUE; ContactFinish: Silver
TP2 TP9 = CMP-0055148-2: Test Point, Multipurpose, Black, TH; Manufacturer: Keystone Electronics; CNHeader: FALSE; Green_Lifecycle: Active; Green_REACh: Passed; CT: TRUE; ContactFinish: Silver
TP3-TP5 = CMP-0055149-2: Test Point, Multipurpose, White, TH; Manufacturer: Keystone Electronics; CNHeader: FALSE; Green_Lifecycle: Active; Green_REACh: Passed; CT: TRUE; ContactFinish: Silver
U1 = CMP-0094622-2: SMBus 2- to 5-Cell Narrow VDC Dual Phase Buck-Boost Battery Charge Controller With System Power Monitor and Processor Hot Monitor; Manufacturer: Texas Instruments; SizeZ_mm: 0.8mm; Min Supply Voltage: 3.5V; Standoff Height: 0mm; Max Supply Voltage: 40V; Number Of Cells: 5; Number Of Outputs: 1; CompType: IC; AEC Category: Q200

## Sheet PMP23637_Hardware.SchDoc: EVM hardware
size 431 x 279 mm; Date: Not shown in title block; ApprovedBy: Not shown in title block; CheckedBy: Not shown in title block; Author: Not shown in title block; CompanyName: Not shown in title block; Engineer: Not shown in title block; Organization: Not shown in title block; Address1: Not shown in title block; Address2: Not shown in title block; Address3: Not shown in title block; Address4: Not shown in title block; DocumentNumber: 2; Revision: Use project parameter SCH_Rev; SheetNumber: 2; SheetTotal: 2; PageSetup: Record=PageOptions¦CenterHorizontal=True¦CenterVertical=True¦PrintScale=1.00¦XCorrection=1.00¦YCorrection=1.00¦PrintKind=0¦BorderSize=5000000¦LeftOffset=0¦BottomOffset=0¦Orientation=2¦PaperLength=1000¦PaperWidth=1000¦Scale=100¦PaperSource=15¦PrintQuality=600¦MediaType=1¦DitherType=10¦PaperKind=Letter¦PrintScaleMode=1
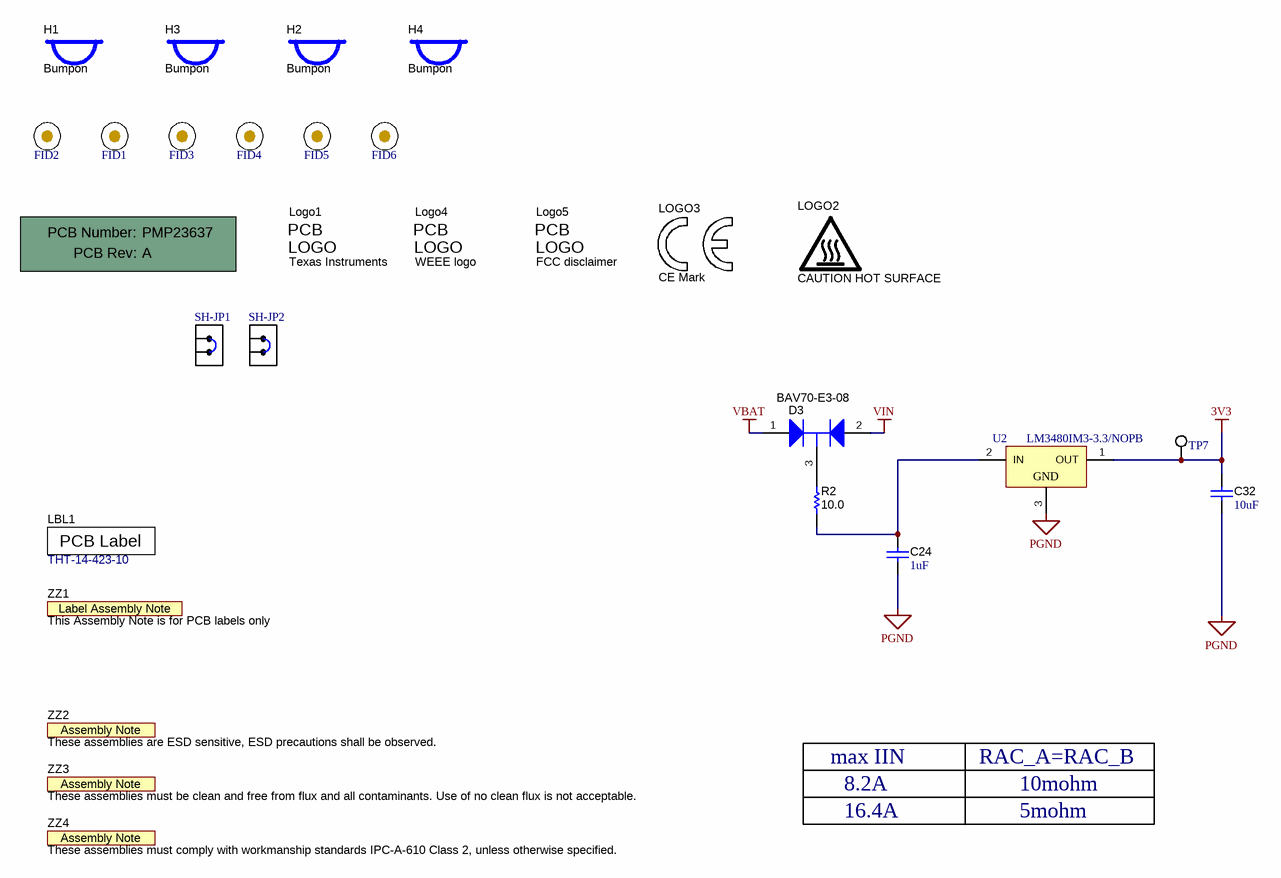
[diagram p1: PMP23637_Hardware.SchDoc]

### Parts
!PCB1  Printed Circuit Board  (value not drawn)  (mechanical)
C24  ValueDisplayed: 1uF  [0603S]  (hidden comment: C1608X5R1H105K080AB)
C32  ValueDisplayed: 10uF  [0603S]  (hidden comment: GRM188R6YA106MA73D)
D3  BAV70-E3-08  [SOT-23L]
FID1  Fiducial  [Fiducial10-20]  (value not drawn)  (no BOM)
FID2  Fiducial  [Fiducial10-20]  (value not drawn)  (no BOM)
FID3  Fiducial  [Fiducial10-20]  (value not drawn)  (no BOM)
FID4  Fiducial  [Fiducial10-20]  (value not drawn)  (no BOM)
FID5  Fiducial  [Fiducial10-20]  (value not drawn)  (no BOM)
FID6  Fiducial  [Fiducial10-20]  (value not drawn)  (no BOM)
H1  Bumpon  [Bumpon_SJ5003Transparent]
H2  Bumpon  [Bumpon_SJ5003Transparent]
H3  Bumpon  [Bumpon_SJ5003Transparent]
H4  Bumpon  [Bumpon_SJ5003Transparent]
LBL1  THT-14-423-10  [Label_650x200]
Logo1  Texas Instruments  [TI_Stacked_Overlay_Small]  (no BOM)
LOGO2  CAUTION HOT SURFACE  [IEC_HotSurface_Small]  (no BOM)
LOGO3  CE Mark  [CE_Mark_5mm]  (no BOM)
Logo4  WEEE logo  [WEEE_Minimum]  (no BOM)
Logo5  FCC disclaimer  [FCC_disclaimer]  (no BOM)
R2  ValueDisplayed: 10.0  [1206L]  (hidden comment: ERJ-8ENF10R0V)
SH-JP1  SNT-100-BK-G  [SNT-100-BK-G]  (value not drawn)
SH-JP2  SNT-100-BK-G  [SNT-100-BK-G]  (value not drawn)
TP7  5015  [Testpoint_Keystone_Miniature]  (value not drawn)
U2  LM3480IM3-3.3/NOPB  [DBZ0003A_N]
ZZ1  This Assembly Note is for PCB labels only  [AssemblyNoteLabel]  (no BOM)
ZZ2  These assemblies are ESD sensitive, ESD precautions shall be observed.  [AssemblyNote]  (no BOM)
ZZ3  These assemblies must be clean and free from flux and all contaminants. Use of no clean flux is not acceptable.  [AssemblyNote]  (no BOM)
ZZ4  These assemblies must comply with workmanship standards IPC-A-610 Class 2, unless otherwise specified.  [AssemblyNote]  (no BOM)

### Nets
3V3: C32.2 TP7.1 U2.1(OUT)
PGND: C24.1 C32.1 U2.3(GND)
VBAT: D3.1(A)
VIN: D3.2(K)
NetC24_2: C24.2 R2.1 U2.2(IN)
NetD3_3: D3.3(C) R2.2

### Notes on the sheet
- max IIN
- RAC_A=RAC_B
- 8.2A
- 16.4A
- 10mohm
- 5mohm

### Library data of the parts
!PCB1 = CMP-0003618-2: Manufacturer: Any; PartNumber: PMP23637; SymbolCreator: a0412235
C24 = CMP-0007011-5: as C33 on sheet PMP23637_MAIN
C32 = CMP-0007355-7: CAP, CERM, 10 uF, 35 V, +/- 20%, X5R, 0603; Manufacturer: Murata; Polarized: N; Value: 10uF; U/M: EA; Cap_F: 10µF; Value1: Unknown; VDC_V: 35V; TaMin_C: -55°C; TaMax_C: 85°C; Cap_Case: 0603; SizeAreaWB_mm2: 4.68; SizeZ_mm: 1; SizeX_mm: 1.6; SizeY_mm: 0.8; SizeArea_mm2: 1.28; AEC Category: Q200; MFG_Status: Temp
D3 = CMP-0077061-2: Diode, Switching, 70 V, 0.25 A, AEC-Q101, SOT-23; Manufacturer: Vishay-Semiconductor; SizeZ_mm: 1.1; AEC Qualified: Y; Value: 70V; SizeY_mm: 3.0; Value2: 1.25V; SizeArea_mm2: 7.5; AEC Category: Q101; SizeAreaWB_mm2: 14.0; Value1: 0.25A; Io_A: 250mA; SizeX_mm: 2.5; Green_REACh: Incomplete; TJmax_C: 150°C; Green_Lifecycle: Not Set
FID1-FID6 = CMP-0077181-1: Fiducial mark.  There is nothing to buy or mount.; SymbolCreator: codlsc
H1-H4 = CMP-0003620-1: Bumpon, Hemisphere, 0.44 X 0.20, Clear; Manufacturer: 3M; PartNumber: SJ-5303 (CLEAR); SymbolCreator: a0412235
LBL1 = CMP-0003625-1: Thermal Transfer Printable Labels, 0.650" W x 0.200" H - 10,000 per roll; Manufacturer: Brady; Note: Size: 0.65" x 0.20 "
Logo1 = CMP-0074838-1: Texas Instrument Corporate Signature; SymbolCreator: a0412235; Library Reference: Logo; Lib Reference: TI_Logo
LOGO2 = CMP-0074837-2: IEC 61010-1 Hot Surface Warning; Manufacturer: Texas Instruments; SymbolCreator: a0412235; CompType: IC; AEC Category: Q200
LOGO3 = CMP-0074844-1: SymbolCreator: a0412235
Logo4 = CMP-0074769-1
Logo5 = CMP-0074847-1: FCC_disclaimer; SymbolCreator: codlsc; Library Reference: Logo
R2 = CMP-0017299-3: RES, 10.0, 1%, 0.25 W, AEC-Q200 Grade 0, 1206; Manufacturer: Panasonic; Value: 10.0; Res_ohm: 10; Value_Code: 10R0; Power_W: 250mW; Value2: 0.25W; VDC_V: 200V; TempCo: 100 ppm/C; EIA_Code: E96; SizeX_mm: 3.2; SizeY_mm: 1.6; SizeZ_mm: 1.35; SizeArea_mm2: 5.12; AEC Qualified: Y; AEC Category: Q200; AEC Grade: 0; SizeAreaWB_mm2: 10.92
SH-JP1 SH-JP2 = CMP-0003623-3: Shunt, 100mil, Gold plated, Black; Manufacturer: Samtec; Alternate Manufacturer: 3M; Alternate PartNumber: 969102-0000-DA; Value: 1x2; Note: You can "mate" this to a header by matching the designator.  i.e. use SH-J3 for header J3
TP7 = CMP-0055152-2: Test Point, Miniature, SMT; Manufacturer: Keystone Electronics; CNHeader: FALSE; Green_Lifecycle: Active; Green_REACh: Passed; CT: TRUE
U2 = CMP-0071020-1: 100 mA, Quasi Low-Dropout Linear Voltage Regulator, 3-pin SOT-23, Pb-Free; Manufacturer: Texas Instruments; CompType: LDO IC; PowerWise: N; PackageTopMarking: L0A*XTT
ZZ1 = CMP-0003616-3: SymbolCreator: a0412235
ZZ2 = CMP-0077236-1: SymbolCreator: codlsc
ZZ3 = CMP-0077237-1: SymbolCreator: codlsc
ZZ4 = CMP-0077238-1: SymbolCreator: codlsc

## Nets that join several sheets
3V3: PMP23637_MAIN (8 pins), PMP23637_Hardware (C32.2 TP7.1 U2.1)
PGND: PMP23637_MAIN (75 pins), PMP23637_Hardware (C24.1 C32.1 U2.3)
VBAT: PMP23637_MAIN (9 pins), PMP23637_Hardware (D3.1)
VIN: PMP23637_MAIN (18 pins), PMP23637_Hardware (D3.2)

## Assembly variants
001: not fitted C23 C35 C36 C37 C38 C49 C52 D2 R4 R13 R18 R19 R25 SH-JP2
